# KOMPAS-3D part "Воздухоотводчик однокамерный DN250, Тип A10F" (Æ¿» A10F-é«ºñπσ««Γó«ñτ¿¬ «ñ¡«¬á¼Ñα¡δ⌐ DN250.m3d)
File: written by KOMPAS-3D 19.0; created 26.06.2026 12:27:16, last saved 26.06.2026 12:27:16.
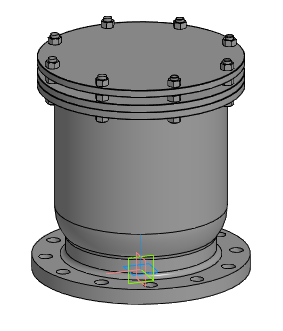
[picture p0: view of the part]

Document properties: Автор: Энергия; Полное имя файла: Z:\3.Личные\kachalov\001_3d для проектировщиков\х.х Тип A10F Воздухоотводчик однокамерный фланцевый\_step\Тип A10F-Воздухоотводчик однокамерный DN250.m3d

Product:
- Part/product: Воздухоотводчик однокамерный DN250  | designation Тип A10F

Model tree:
1. Операция без истории:1  (labels: Тип A10F; Воздухоотводчик однокамерный DN250)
